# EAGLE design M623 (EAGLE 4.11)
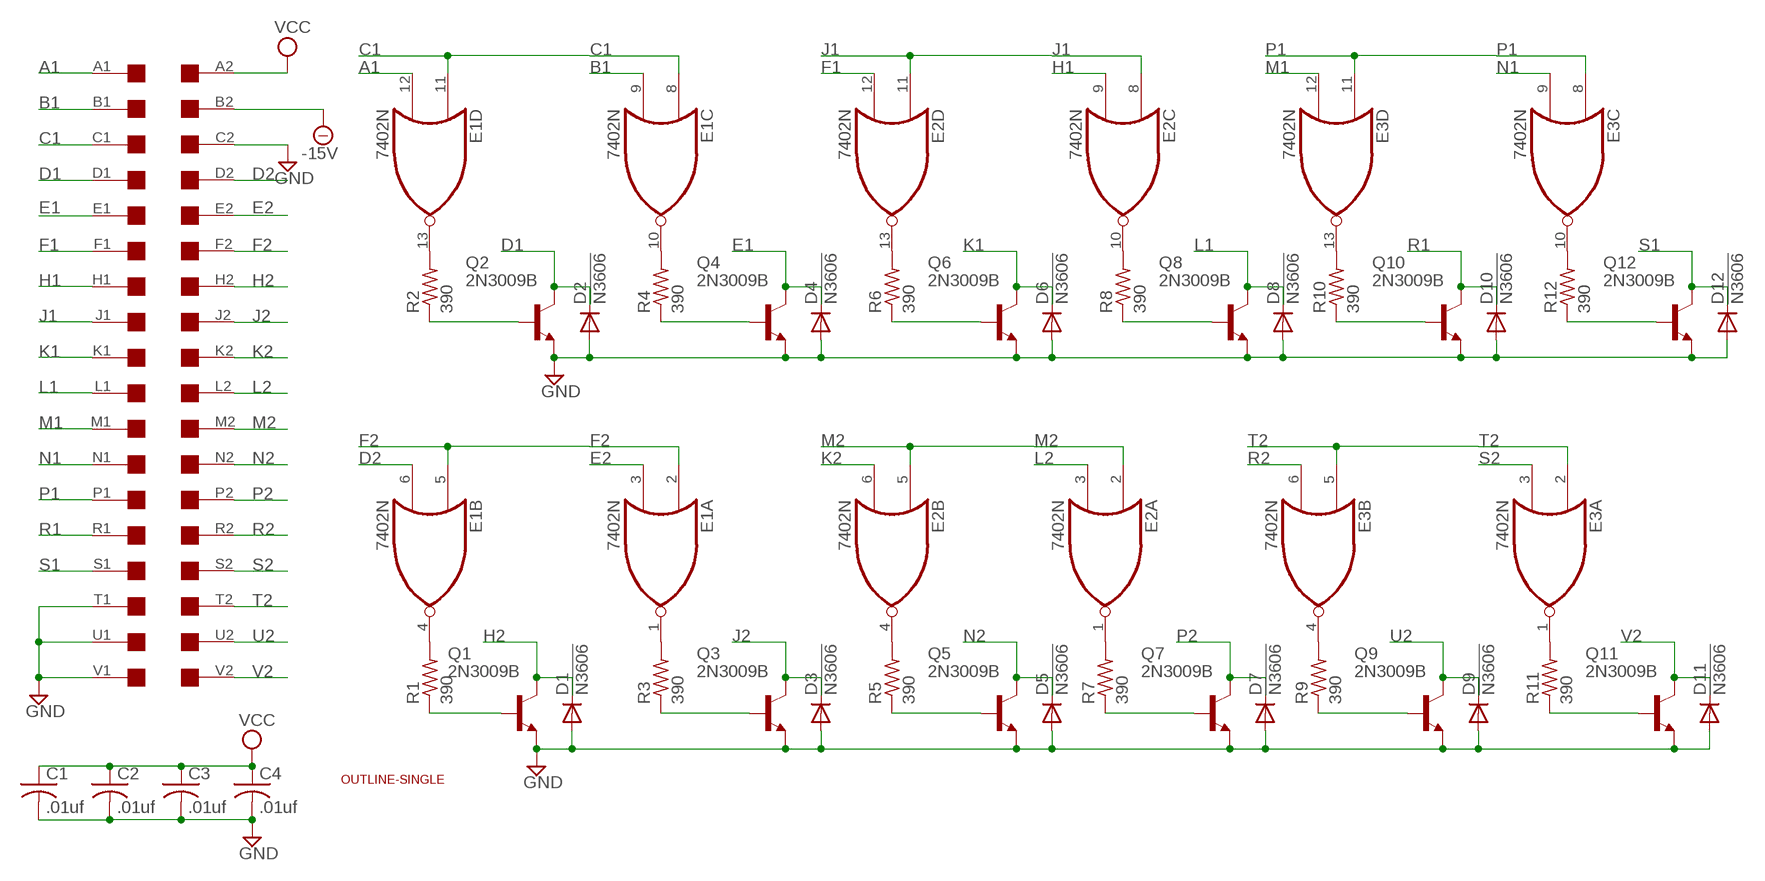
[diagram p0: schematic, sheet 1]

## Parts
C1  .01uf  C-US050-025X075  [C050-025X075]
C2  .01uf  C-US050-025X075  [C050-025X075]
C3  .01uf  C-US050-025X075  [C050-025X075]
C4  .01uf  C-US050-025X075  [C050-025X075]
D1  !N3606  1N4148  [DO35-10]
D2  !N3606  1N4148  [DO35-10]
D3  !N3606  1N4148  [DO35-10]
D4  !N3606  1N4148  [DO35-10]
D5  !N3606  1N4148  [DO35-10]
D6  !N3606  1N4148  [DO35-10]
D7  !N3606  1N4148  [DO35-10]
D8  !N3606  1N4148  [DO35-10]
D9  !N3606  1N4148  [DO35-10]
D10  !N3606  1N4148  [DO35-10]
D11  !N3606  1N4148  [DO35-10]
D12  !N3606  1N4148  [DO35-10]
E1  7402N  [DIL14]
E2  7402N  [DIL14]
E3  7402N  [DIL14]
Q1  2N3009B  2N1613-NPN-TO39-EBC  [TO39]
Q2  2N3009B  2N1613-NPN-TO39-EBC  [TO39]
Q3  2N3009B  2N1613-NPN-TO39-EBC  [TO39]
Q4  2N3009B  2N1613-NPN-TO39-EBC  [TO39]
Q5  2N3009B  2N1613-NPN-TO39-EBC  [TO39]
Q6  2N3009B  2N1613-NPN-TO39-EBC  [TO39]
Q7  2N3009B  2N1613-NPN-TO39-EBC  [TO39]
Q8  2N3009B  2N1613-NPN-TO39-EBC  [TO39]
Q9  2N3009B  2N1613-NPN-TO39-EBC  [TO39]
Q10  2N3009B  2N1613-NPN-TO39-EBC  [TO39]
Q11  2N3009B  2N1613-NPN-TO39-EBC  [TO39]
Q12  2N3009B  2N1613-NPN-TO39-EBC  [TO39]
R1  390  R-US_0207/10  [0207/10]
R2  390  R-US_0207/10  [0207/10]
R3  390  R-US_0207/10  [0207/10]
R4  390  R-US_0207/10  [0207/10]
R5  390  R-US_0207/10  [0207/10]
R6  390  R-US_0207/10  [0207/10]
R7  390  R-US_0207/10  [0207/10]
R8  390  R-US_0207/10  [0207/10]
R9  390  R-US_0207/10  [0207/10]
R10  390  R-US_0207/10  [0207/10]
R11  390  R-US_0207/10  [0207/10]
R12  390  R-US_0207/10  [0207/10]
U$1  OUTLINE-SINGLE  [SINGLE]
U$4  SINGLE  [EDGE-CON2]

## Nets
-15V: U$4.B2
A1: E1.12(D:I1) U$4.A1
B1: E1.9(C:I1) U$4.B1
C1: E1.8(C:I0) E1.11(D:I0) U$4.C1
D1: D2.C Q2.3(C) U$4.D1
D2: E1.6(B:I1) U$4.D2
E1: D4.C Q4.3(C) U$4.E1
E2: E1.3(A:I1) U$4.E2
F1: E2.12(D:I1) U$4.F1
F2: E1.2(A:I0) E1.5(B:I0) U$4.F2
GND: C1.2 C2.2 C3.2 C4.2 D1.A D2.A D3.A D4.A D5.A D6.A D7.A D8.A D9.A D10.A D11.A D12.A Q1.1(E) Q2.1(E) Q3.1(E) Q4.1(E) Q5.1(E) Q6.1(E) Q7.1(E) Q8.1(E) Q9.1(E) Q10.1(E) Q11.1(E) Q12.1(E) U$4.C2 U$4.T1 U$4.U1 U$4.V1
H1: E2.9(C:I1) U$4.H1
H2: D1.C Q1.3(C) U$4.H2
J1: E2.8(C:I0) E2.11(D:I0) U$4.J1
J2: D3.C Q3.3(C) U$4.J2
K1: D6.C Q6.3(C) U$4.K1
K2: E2.6(B:I1) U$4.K2
L1: D8.C Q8.3(C) U$4.L1
L2: E2.3(A:I1) U$4.L2
M1: E3.12(D:I1) U$4.M1
M2: E2.2(A:I0) E2.5(B:I0) U$4.M2
N1: E3.9(C:I1) U$4.N1
N2: D5.C Q5.3(C) U$4.N2
N$1: E1.13(D:O) R2.2
N$2: Q2.2(B) R2.1
N$3: E1.4(B:O) R1.2
N$4: Q1.2(B) R1.1
N$12: E1.10(C:O) R4.2
N$13: E1.1(A:O) R3.2
N$14: E2.4(B:O) R5.2
N$15: E2.13(D:O) R6.2
N$16: E2.1(A:O) R7.2
N$17: E2.10(C:O) R8.2
N$18: E3.4(B:O) R9.2
N$19: E3.13(D:O) R10.2
N$20: E3.1(A:O) R11.2
N$21: E3.10(C:O) R12.2
N$22: Q12.2(B) R12.1
N$24: Q4.2(B) R4.1
N$25: Q6.2(B) R6.1
N$26: Q8.2(B) R8.1
N$27: Q10.2(B) R10.1
N$28: Q3.2(B) R3.1
N$29: Q5.2(B) R5.1
N$30: Q7.2(B) R7.1
N$31: Q9.2(B) R9.1
N$32: Q11.2(B) R11.1
P1: E3.8(C:I0) E3.11(D:I0) U$4.P1
P2: D7.C Q7.3(C) U$4.P2
R1: D10.C Q10.3(C) U$4.R1
R2: E3.6(B:I1) U$4.R2
S1: D12.C Q12.3(C) U$4.S1
S2: E3.3(A:I1) U$4.S2
T2: E3.2(A:I0) E3.5(B:I0) U$4.T2
U2: D9.C Q9.3(C) U$4.U2
V2: D11.C Q11.3(C) U$4.V2
VCC: C1.1 C2.1 C3.1 C4.1 U$4.A2

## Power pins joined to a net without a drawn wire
GND: E1.7(P:GND) E2.7(P:GND) E3.7(P:GND)
VCC: E1.14(P:VCC) E2.14(P:VCC) E3.14(P:VCC)

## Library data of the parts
C1-C4 = rcl:C-US: CAPACITOR, American symbol
D1-D12 = diode:1N4148: DIODE
E1-E3 = 74xx-us:74*02: Quad 2-input NOR gate
Q1-Q12 = transistor:*-NPN-: NPN Transistror
R1-R12 = rcl:R-US_: RESISTOR, American symbol
U$1 = dec-con:OUTLINE-*: Board outlines for DEC boards.
U$4 = dec-con:SINGLE: Single-Height DEC board

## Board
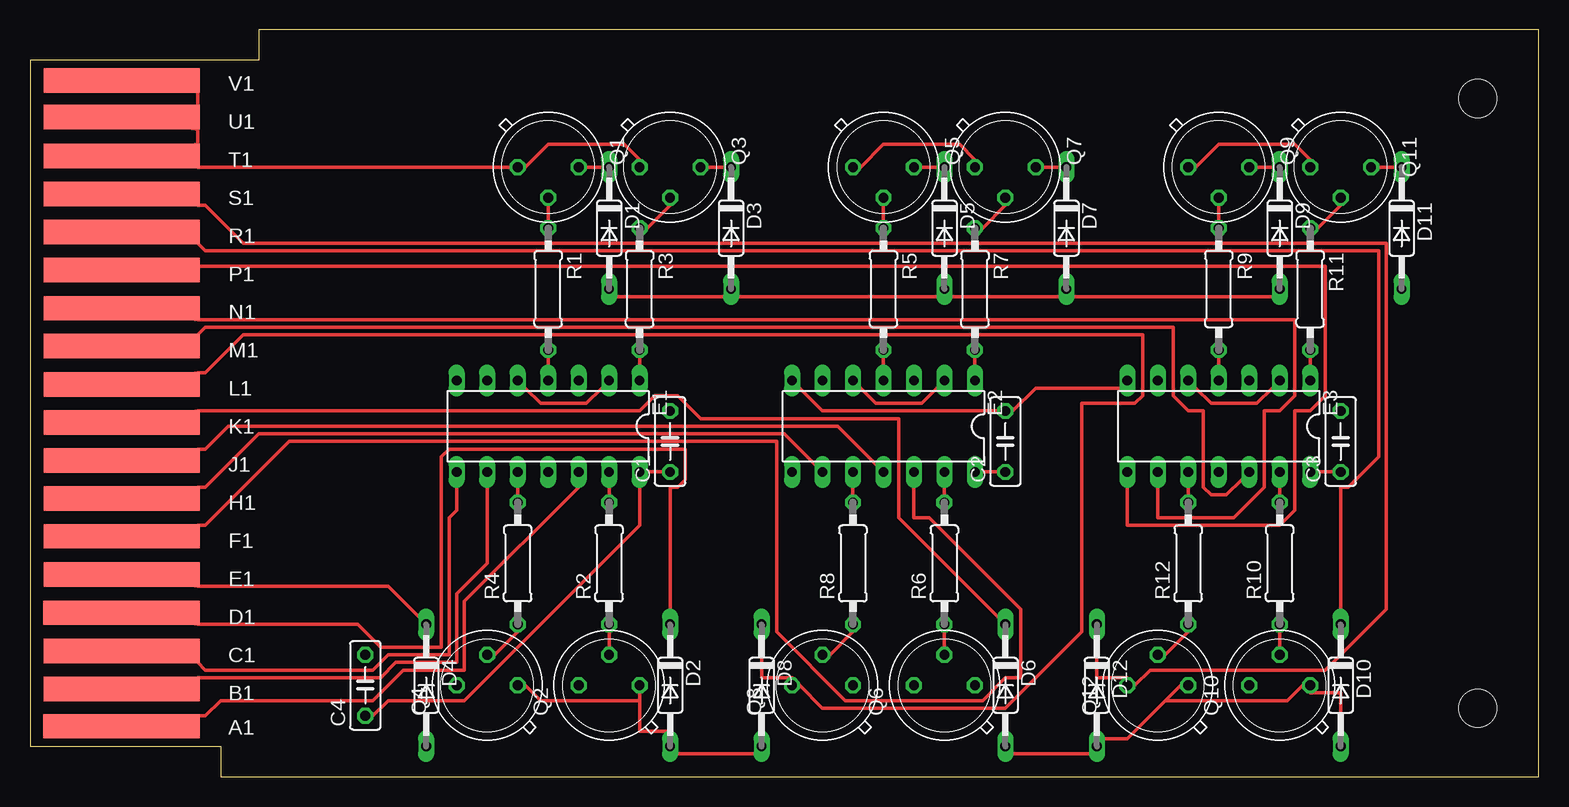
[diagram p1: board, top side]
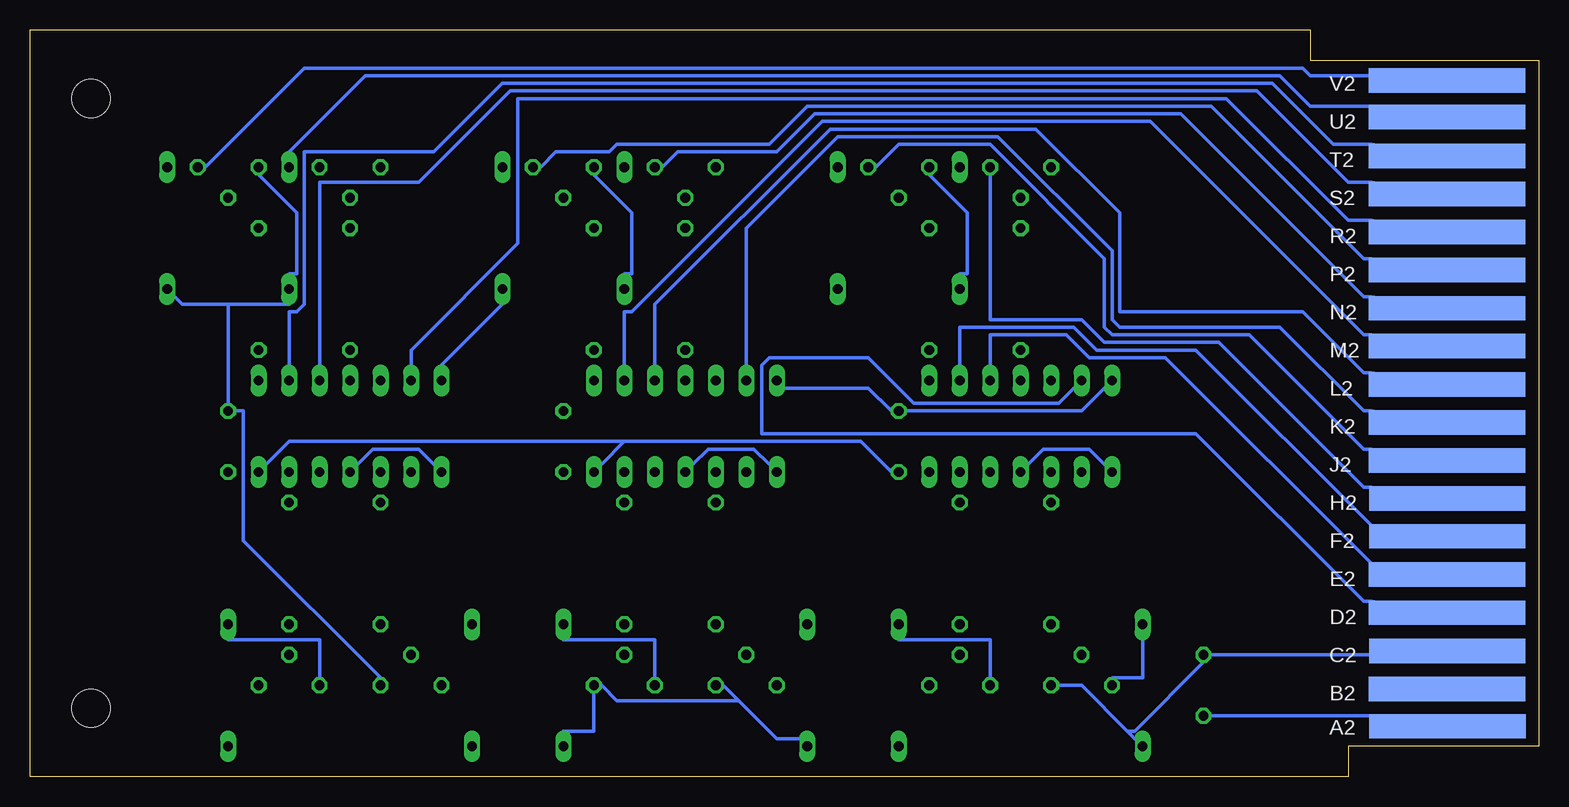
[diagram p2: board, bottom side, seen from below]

Size 125.73 x 62.23 mm. Coordinates in mm from the lower left corner, seen from the top.
Copper layers (1*16): Top 0.035mm / dielectric 1.5mm / Bottom 0.035mm
Design rules "10mils": minimum track width 12mil, minimum drill 28mil, track to track 10mil, track to pad 10mil, pad to pad 10mil, via to via 10mil, smd to smd 10mil, copper to edge 25mil, drill to drill 10mil, minimum pad ring 10mil, minimum via ring 8mil, stop-mask expansion 0mil, vias tented up to drill 0mil, thermal gap 10mil

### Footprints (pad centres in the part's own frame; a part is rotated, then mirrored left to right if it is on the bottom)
C050-025X075 = drill 0.813 octagon: 1 -2.54,0; 2 2.54,0
DO35-10 = drill 0.813 long: A 5.08,0; C -5.08,0
DIL14 = drill 0.813 long: 1 -7.62,-3.81; 2 -5.08,-3.81; 3 -2.54,-3.81; 4 0,-3.81; 5 2.54,-3.81; 6 5.08,-3.81; 7 7.62,-3.81; 8 7.62,3.81; 9 5.08,3.81; 10 2.54,3.81; 11 0,3.81; 12 -2.54,3.81; 13 -5.08,3.81; 14 -7.62,3.81
TO39 = drill 0.813 octagon: 1 0,-2.54; 2 2.54,0; 3 0,2.54
0207/10 = drill 0.813 octagon: 1 -5.08,0; 2 5.08,0
SINGLE = hole 3.175: 120.65,56.515; 120.65,5.715
EDGE-CON2 = smd 13.017 x 2.032: A1 7.633,4.207; B1 7.639,7.327; C1 7.636,10.489; D1 7.633,13.665; E1 7.642,16.84; F1 7.642,20.041; H1 7.642,23.19; J1 7.642,26.34; K1 7.642,29.515; L1 7.642,32.69; M1 7.642,35.89; N1 7.642,39.04; P1 7.642,42.24; R1 7.642,45.39; S1 7.642,48.565; T1 7.642,51.74; U1 7.642,54.966; V1 7.642,58.026 | smd 13.017 x 2.032 bottom: A2 7.614,4.207; B2 7.642,7.328; C2 7.617,10.49; D2 7.642,13.665; E2 7.642,16.84; F2 7.617,20.041; H2 7.617,23.19; J2 7.642,26.34; K2 7.642,29.515; L2 7.642,32.69; M2 7.642,35.89; N2 7.642,39.04; P2 7.642,42.24; R2 7.642,45.39; S2 7.642,48.565; T2 7.642,51.74; U2 7.642,54.966; V2 7.642,58.026

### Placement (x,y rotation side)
C1  53.34,27.94 90 top
C2  81.28,27.94 90 top
C3  109.22,27.94 90 top
C4  27.94,7.62 90 top
D1  48.26,45.72 270 top
D2  53.34,7.62 270 top
D3  58.42,45.72 270 top
D4  33.02,7.62 270 top
D5  76.2,45.72 270 top
D6  81.28,7.62 270 top
D7  86.36,45.72 270 top
D8  60.96,7.62 270 top
D9  104.14,45.72 270 top
D10  109.22,7.62 270 top
D11  114.3,45.72 270 top
D12  88.9,7.62 270 top
E1  43.18,29.21 180 top
E2  71.12,29.21 180 top
E3  99.06,29.21 180 top
Q1  43.18,50.8 270 top
Q2  48.26,7.62 90 top
Q3  53.34,50.8 270 top
Q4  38.1,7.62 90 top
Q5  71.12,50.8 270 top
Q6  76.2,7.62 90 top
Q7  81.28,50.8 270 top
Q8  66.04,7.62 90 top
Q9  99.06,50.8 270 top
Q10  104.14,7.62 90 top
Q11  109.22,50.8 270 top
Q12  93.98,7.62 90 top
R1  43.18,40.64 270 top
R2  48.26,17.78 90 top
R3  50.8,40.64 270 top
R4  40.64,17.78 90 top
R5  71.12,40.64 270 top
R6  76.2,17.78 90 top
R7  78.74,40.64 270 top
R8  68.58,17.78 90 top
R9  99.06,40.64 270 top
R10  104.14,17.78 90 top
R11  106.68,40.64 270 top
R12  96.52,17.78 90 top
U$1  0,0 0 top
U$4  0,0 0 top

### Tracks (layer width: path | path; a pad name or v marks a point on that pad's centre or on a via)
A1
  Top 0.305: E1.12 45.72,24.13 36.2,14.61 36.2,8.89 31.12,8.89 28.58,6.35 15.88,6.35 14.61,5.08 13.97,5.08 U$4.A1
B1
  Top 0.305: E1.9 38.1,24.13 38.1,17.78 35.56,15.24 35.56,9.53 30.48,9.53 29.21,8.26 13.97,8.26 U$4.B1
C1
  Top 0.305: E1.8 35.56,24.13 35.56,22.23 34.93,21.59 34.93,10.16 29.85,10.16 28.58,8.89 14.61,8.89 13.97,9.53 U$4.C1
  Bottom 0.305: E1.8 36.2,26.04 37.47,27.3 41.28,27.3 42.55,26.04 E1.11
D1
  Top 0.305: D2.C 53.34,13.97 53.34,24.13 53.98,24.13 54.61,24.77 54.61,27.3 34.93,27.3 34.29,26.67 34.29,10.79 29.21,10.79 27.31,12.7 13.97,12.7 U$4.D1
  Bottom 0.305: Q2.3 45.72,8.26 45.72,11.43 53.34,11.43 D2.C
D2
  Bottom 0.305: E1.6 38.74,32.38 40.01,31.11 52.07,31.11 55.88,34.92 64.14,34.92 64.77,34.29 64.77,28.57 28.58,28.57 14.61,14.61 13.97,14.61 U$4.D2
E1
  Top 0.305: D4.C 32.39,13.34 29.85,15.88 13.97,15.88 U$4.E1
  Bottom 0.305: D4.C 33.02,11.43 33.02,8.26 35.56,8.26 Q4.3
E2
  Bottom 0.305: E1.3 45.72,34.29 45.72,36.83 39.37,36.83 37.47,34.92 31.12,34.92 13.97,17.78 U$4.E2
F1
  Top 0.305: E2.12 73.66,24.13 73.66,21.59 74.93,21.59 82.55,13.97 82.55,8.26 81.28,8.26 79.38,6.35 67.95,6.35 62.23,12.06 62.23,27.94 21.59,27.94 14.61,20.95 13.97,20.95 U$4.F1
F2
  Top 0.305: E1.5 41.28,32.38 42.55,31.11 46.36,31.11 47.63,32.38 E1.2
  Bottom 0.305: E1.2 48.26,34.29 48.26,37.47 38.74,37.47 36.83,35.56 28.58,35.56 13.97,20.95 U$4.F2
GND
  Top 0.305: D10.A 109.22,3.81 109.22,6.99 106.68,6.99 Q10.1 106.05,7.62 104.78,6.35 94.62,6.35 | D6.A 81.92,1.91 88.27,1.91 D12.A 89.54,3.17 91.44,3.17 94.62,6.35 | 94.62,6.35 95.89,7.62 Q12.1 | 50.8,6.35 50.8,3.81 53.34,3.81 D2.A 53.98,1.91 60.33,1.91 D8.A | 50.8,6.35 50.8,6.99 Q2.1 | 50.8,6.35 42.55,6.35 41.28,7.62 Q4.1 | Q9.1 97.16,50.8 99.06,52.7 105.41,52.7 106.68,51.44 Q11.1 | U$4.V1 13.97,57.15 13.97,55.88 U$4.U1 13.97,53.98 13.97,52.7 U$4.T1 13.97,50.8 40.01,50.8 Q1.1 41.28,50.8 43.18,52.7 49.53,52.7 50.8,51.44 Q3.1 | E3.7 90.81,32.38 83.82,32.38 81.92,30.48 C2.2 80.65,30.48 66.04,30.48 64.14,32.38 E2.7 | Q5.1 69.22,50.8 71.12,52.7 77.47,52.7 78.74,51.44 Q7.1 | D1.A 48.9,40.01 57.79,40.01 D3.A 59.06,40.01 75.57,40.01 D5.A 76.84,40.01 85.73,40.01 D7.A 87,40.01 103.51,40.01 D9.A
  Bottom 0.305: D6.A 81.28,3.81 78.74,3.81 78.74,6.99 Q6.1 78.11,7.62 76.84,6.35 66.68,6.35 | 34.29,3.81 38.1,7.62 40.01,7.62 Q4.1 | 34.29,3.81 33.66,3.17 D4.A | 34.29,3.81 33.66,3.81 27.94,9.53 C4.2 27.31,10.16 13.97,10.16 U$4.C2 | 66.68,6.35 63.5,3.17 61.6,3.17 D8.A | 66.68,6.35 67.95,7.62 Q8.1 | 109.22,39.37 109.22,31.11 C3.2 108.59,30.48 107.95,30.48 107.95,19.68 96.52,8.26 Q12.1 | 109.22,39.37 104.14,39.37 D9.A 104.14,41.91 103.51,41.91 103.51,46.99 106.68,50.16 Q11.1 | 109.22,39.37 113.03,39.37 113.67,40.01 D11.A | E2.7 62.87,32.38 55.88,32.38 53.98,30.48 C1.2 52.71,30.48 38.1,30.48 36.2,32.38 E1.7 | Q3.1 50.8,50.16 47.63,46.99 47.63,41.91 48.26,41.91 D1.A | Q7.1 78.74,50.16 75.57,46.99 75.57,41.91 76.2,41.91 D5.A | E3.7 91.44,34.29 86.36,39.37 D7.A
H1
  Top 0.305: E2.9 65.41,26.04 62.87,28.57 19.05,28.57 14.61,24.13 13.97,24.13 U$4.H1
H2
  Top 0.305: Q1.3 46.36,50.8 47.63,50.8 D1.C
  Bottom 0.305: Q1.3 45.72,50.16 45.72,38.1 38.1,38.1 36.2,36.2 26.67,36.2 14.61,24.13 13.97,24.13 U$4.H2
J1
  Top 0.305: E2.11 70.49,26.04 67.31,29.21 16.51,29.21 14.61,27.3 13.97,27.3 U$4.J1
  Bottom 0.305: E2.8 64.14,26.04 65.41,27.3 69.22,27.3 70.49,26.04 E2.11
J2
  Top 0.305: Q3.3 56.52,50.8 57.79,50.8 D3.C
  Bottom 0.305: Q3.3 55.25,50.8 53.34,52.7 45.72,52.7 36.2,43.18 36.2,37.47 35.56,36.83 24.13,36.83 14.61,27.3 13.97,27.3 U$4.J2
K1
  Top 0.305: D6.C 80.65,13.34 72.39,21.59 72.39,29.84 55.88,29.84 53.98,31.75 52.07,31.75 50.8,30.48 13.97,30.48 U$4.K1
  Bottom 0.305: Q6.3 73.66,8.26 73.66,11.43 81.28,11.43 D6.C
K2
  Bottom 0.305: E2.6 66.04,34.29 66.04,45.72 58.42,53.34 45.09,53.34 35.56,43.81 35.56,38.1 34.93,37.47 21.59,37.47 14.61,30.48 13.97,30.48 U$4.K2
L1
  Top 0.305: D8.C 60.96,11.43 60.96,8.26 63.5,8.26 Q8.3 64.14,7.62 66.04,5.71 81.28,5.71 87.63,12.06 87.63,31.11 92.08,31.11 92.71,31.75 92.71,36.83 17.78,36.83 14.61,33.66 13.97,33.66 U$4.L1
L2
  Bottom 0.305: E2.3 73.66,34.29 73.66,39.37 59.06,53.98 41.91,53.98 34.93,46.99 34.93,38.73 19.69,38.73 14.61,33.66 13.97,33.66 U$4.L2
M1
  Top 0.305: E3.12 100.97,24.77 99.7,23.5 98.43,23.5 97.79,24.13 97.79,30.48 96.52,30.48 95.25,31.75 95.25,37.47 14.61,37.47 13.97,36.83 U$4.M1
M2
  Top 0.305: E2.5 69.22,32.38 70.49,31.11 74.3,31.11 75.57,32.38 E2.2
  Bottom 0.305: E2.2 76.2,34.29 76.2,38.73 75.57,38.73 59.69,54.61 32.39,54.61 14.61,36.83 13.97,36.83 U$4.M2
N1
  Top 0.305: U$4.N1 13.97,38.1 105.41,38.1 105.41,31.75 104.14,30.48 102.87,30.48 102.87,24.13 100.33,21.59 93.98,21.59 93.98,24.13 E3.9
N2
  Top 0.305: Q5.3 74.3,50.8 75.57,50.8 D5.C
  Bottom 0.305: Q5.3 73.03,50.8 71.76,52.07 63.5,52.07 60.33,55.24 29.85,55.24 14.61,40.01 13.97,40.01 U$4.N2
N$1
  Top 0.305: R2.2 48.26,23.5 48.26,24.13 E1.13
N$2
  Top 0.305: Q2.2 48.26,10.79 48.26,12.06 R2.1
N$3
  Top 0.305: E1.4 43.18,34.29 43.18,34.92 R1.2
N$4
  Top 0.305: R1.1 43.18,46.35 43.18,47.62 Q1.2
N$12
  Top 0.305: R4.2 40.64,23.5 40.64,24.13 E1.10
N$13
  Top 0.305: E1.1 50.8,34.29 50.8,34.92 R3.2
N$14
  Top 0.305: E2.4 71.12,34.29 71.12,34.92 R5.2
N$15
  Top 0.305: R6.2 76.2,23.5 76.2,24.13 E2.13
N$16
  Top 0.305: E2.1 78.74,34.29 78.74,34.92 R7.2
N$17
  Top 0.305: R8.2 68.58,23.5 68.58,24.13 E2.10
N$18
  Top 0.305: E3.4 99.06,34.29 99.06,34.92 R9.2
N$19
  Top 0.305: R10.2 104.14,23.5 104.14,24.13 E3.13
N$20
  Top 0.305: E3.1 106.68,34.29 106.68,34.92 R11.2
N$21
  Top 0.305: R12.2 96.52,23.5 96.52,24.13 E3.10
N$22
  Top 0.305: Q12.2 94.62,10.16 96.52,12.06 R12.1
N$24
  Top 0.305: Q4.2 38.74,10.16 40.64,12.06 R4.1
N$25
  Top 0.305: Q6.2 76.2,10.79 76.2,12.06 R6.1
N$26
  Top 0.305: Q8.2 66.68,10.16 68.58,12.06 R8.1
N$27
  Top 0.305: Q10.2 104.14,10.79 104.14,12.06 R10.1
N$28
  Top 0.305: R3.1 51.44,45.72 53.34,47.62 Q3.2
N$29
  Top 0.305: R5.1 71.12,46.35 71.12,47.62 Q5.2
N$30
  Top 0.305: R7.1 79.38,45.72 81.28,47.62 Q7.2
N$31
  Top 0.305: R9.1 99.06,46.35 99.06,47.62 Q9.2
N$32
  Top 0.305: R11.1 107.32,45.72 109.22,47.62 Q11.2
P1
  Top 0.305: E3.8 91.44,24.13 91.44,20.95 104.14,20.95 105.41,22.23 105.41,30.48 106.68,30.48 107.95,31.75 107.95,42.55 13.97,42.55 U$4.P1
  Bottom 0.305: E3.8 92.08,26.04 93.35,27.3 97.16,27.3 98.43,26.04 E3.11
P2
  Top 0.305: Q7.3 84.46,50.8 85.73,50.8 D7.C
  Bottom 0.305: Q7.3 83.19,50.8 81.92,52.07 77.47,52.07 76.84,52.7 64.14,52.7 60.96,55.88 27.31,55.88 14.61,43.18 13.97,43.18 U$4.P2
R1
  Top 0.305: D10.C 109.22,13.97 109.22,24.13 109.86,24.13 112.4,26.67 112.4,43.81 14.61,43.81 13.97,44.45 U$4.R1
  Bottom 0.305: Q10.3 101.6,8.26 101.6,11.43 109.22,11.43 D10.C
R2
  Bottom 0.305: E3.6 93.98,34.29 93.98,35.56 85.09,44.45 85.09,56.52 26.04,56.52 15.88,46.35 13.97,46.35 U$4.R2
S1
  Top 0.305: D12.C 88.9,11.43 88.9,8.26 91.44,8.26 Q12.3 92.08,7.62 93.35,8.89 107.95,8.89 113.03,13.97 113.03,44.45 17.78,44.45 14.61,47.62 13.97,47.62 U$4.S1
S2
  Bottom 0.305: E3.3 101.6,34.29 101.6,49.53 93.35,49.53 85.73,57.15 23.5,57.15 15.88,49.53 13.97,49.53 U$4.S2
T2
  Top 0.305: E3.5 97.16,32.38 98.43,31.11 102.24,31.11 103.51,32.38 E3.2
  Bottom 0.305: E3.2 104.14,34.29 104.14,38.73 103.51,38.73 102.87,39.37 102.87,52.07 92.08,52.07 86.36,57.78 22.23,57.78 17.15,52.7 13.97,52.7 U$4.T2
U2
  Top 0.305: Q9.3 102.24,50.8 103.51,50.8 D9.C
  Bottom 0.305: D9.C 104.14,52.07 97.79,58.42 21.59,58.42 19.05,55.88 13.97,55.88 U$4.U2
V2
  Top 0.305: Q11.3 112.4,50.8 113.67,50.8 D11.C
  Bottom 0.305: Q11.3 111.13,50.8 102.87,59.05 19.69,59.05 19.05,58.42 13.97,58.42 U$4.V2
VCC
  Top 0.305: E3.14 107.32,25.4 108.59,25.4 C3.1 | C1.1 52.71,25.4 51.44,25.4 E1.14 50.8,24.13 50.8,20.95 36.2,6.35 29.85,6.35 28.58,5.08 C4.1 | E2.14 79.38,25.4 80.65,25.4 C2.1
  Bottom 0.305: C4.1 27.31,5.08 13.97,5.08 U$4.A2 | 76.2,27.94 56.52,27.94 53.98,25.4 C1.1 | 76.2,27.94 78.11,26.04 E2.14 | 76.2,27.94 104.14,27.94 106.05,26.04 E3.14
